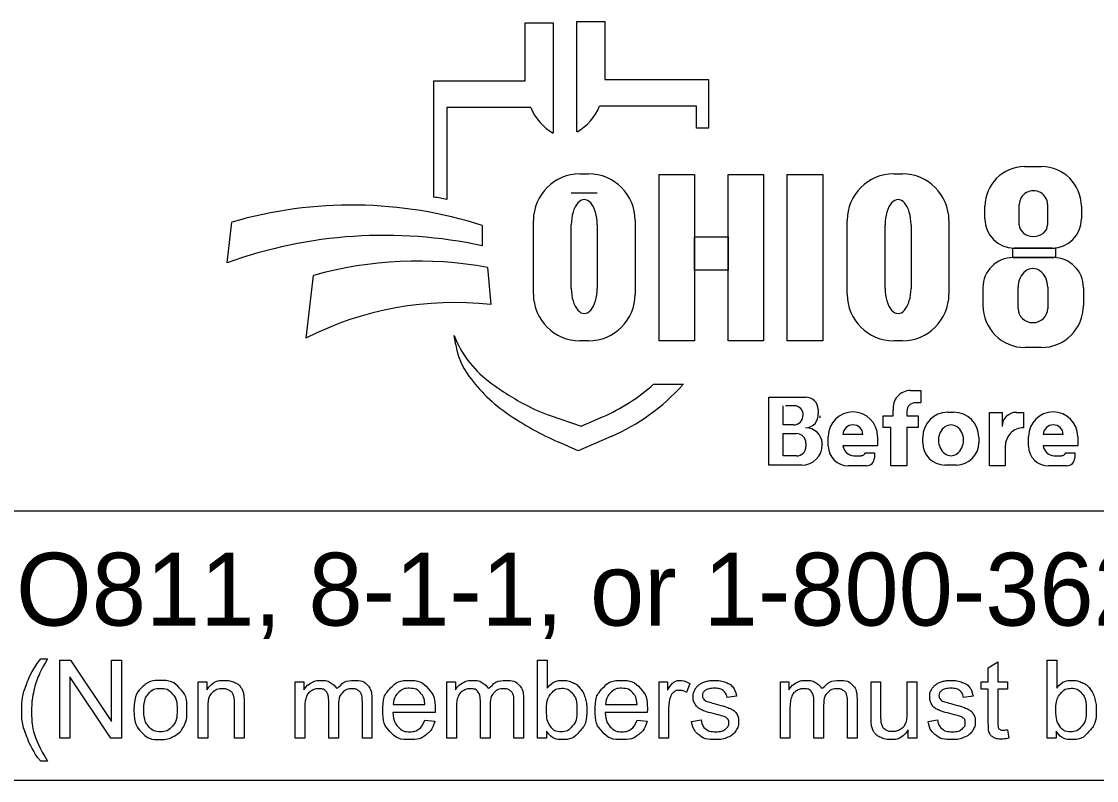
# Model space of a CAD drawing. Extents: x 0 to 34.3, y -4.1 to 22.
# Drawn here: x 10.115 to 12.181, y 7.738 to 9.198 of the extents above; entities that cross this region are included whole.
import ezdxf

# ---------------------------------------------------------------- set-up
doc = ezdxf.new("R2010")
doc.units = 0
doc.layers.add('GM_X_Adjacent_County', color=7, linetype='Continuous')
doc.layers.add('GM_X_Township', color=7, linetype='Continuous')

msp = doc.modelspace()

# ---------------------------------------------------------------- linework, layer by layer
at = {"layer": 'GM_X_Adjacent_County'}
for p, q in [((11.083, 9.0839), (11.083, 9.1953)), ((11.083, 9.1953), (11.1366, 9.1953)), ((11.1366, 9.1953), (11.1366, 8.9833)), ((11.1823, 8.9856), (11.1823, 9.1977)), ((11.1823, 9.1977), (11.2359, 9.1977)), ((11.2359, 9.1977), (11.2359, 9.0862)), ((10.907, 8.86), (10.907, 9.0839)), ((10.907, 9.0839), (11.083, 9.0839)), ((11.2359, 9.0862), (11.4352, 9.0862)), ((11.4352, 9.0862), (11.4352, 8.9924)), ((10.9323, 9.0324), (10.9323, 8.8556)), ((11.0934, 9.0324), (10.9323, 9.0324)), ((11.4119, 9.0347), (11.2255, 9.0347)), ((11.4119, 8.9924), (11.4119, 9.0347)), ((11.4352, 8.9924), (11.4119, 8.9924)), ((11.188, 8.9047), (11.2045, 8.9047)), ((11.791, 8.9047), (11.8076, 8.9047)), ((12.0426, 8.9187), (12.0753, 8.9187)), ((11.2212, 8.8677), (11.1714, 8.8677)), ((12.0324, 8.8067), (12.0324, 8.846)), ((12.0866, 8.846), (12.0866, 8.8067)), ((11.9663, 8.8181), (11.9663, 8.8424)), ((12.1516, 8.8424), (12.1516, 8.8181)), ((10.5097, 8.7337), (10.5191, 8.8118)), ((11.0003, 8.8053), (11.0003, 8.7665)), ((11.0985, 8.6732), (11.0985, 8.8152)), ((11.1714, 8.6846), (11.1714, 8.8069)), ((11.2212, 8.8069), (11.2212, 8.6846)), ((11.294, 8.8152), (11.294, 8.6732)), ((11.7016, 8.6732), (11.7016, 8.8152)), ((11.7745, 8.6846), (11.7745, 8.8069)), ((11.8243, 8.8069), (11.8243, 8.6846)), ((11.897, 8.8152), (11.897, 8.6732)), ((12.0956, 8.7621), (12.0223, 8.7621)), ((12.0204, 8.7438), (12.0978, 8.7438)), ((11.0103, 8.7247), (11.0165, 8.6537)), ((10.6615, 8.5891), (10.6762, 8.7093)), ((11.9626, 8.6518), (11.9626, 8.6859)), ((12.03, 8.6459), (12.03, 8.6868)), ((12.0869, 8.6868), (12.0869, 8.6459)), ((12.1557, 8.6859), (12.1557, 8.6518)), ((10.9492, 8.5762), (10.9461, 8.5942)), ((11.2045, 8.5837), (11.188, 8.5837)), ((11.8076, 8.5837), (11.791, 8.5837)), ((12.0747, 8.5709), (12.0435, 8.5709)), ((11.3295, 8.5004), (11.3869, 8.5004)), ((11.5508, 8.3446), (11.5508, 8.4753)), ((11.5508, 8.4753), (11.6219, 8.4753)), ((11.8234, 8.4881), (11.8428, 8.4881)), ((11.8428, 8.4881), (11.8428, 8.4651)), ((11.5787, 8.4219), (11.5787, 8.4588)), ((11.6039, 8.4588), (11.5827, 8.4588)), ((11.6457, 8.4516), (11.6457, 8.4437)), ((11.7901, 8.4397), (11.7901, 8.4502)), ((11.8428, 8.4647), (11.8327, 8.4647)), ((11.131, 8.44), (11.1905, 8.4195)), ((11.1905, 8.4195), (11.2315, 8.4373)), ((11.7708, 8.4168), (11.7708, 8.4397)), ((11.7708, 8.4397), (11.7901, 8.4397)), ((11.8162, 8.4482), (11.8162, 8.4397)), ((11.8162, 8.4397), (11.8377, 8.4397)), ((11.8377, 8.4397), (11.8377, 8.4168)), ((11.8946, 8.4463), (11.9067, 8.4463)), ((11.9748, 8.3434), (11.9748, 8.4461)), ((11.9748, 8.4461), (11.9994, 8.4461)), ((11.9994, 8.4461), (11.9994, 8.4192)), ((12.0266, 8.4461), (12.0405, 8.4461)), ((12.0405, 8.4461), (12.0405, 8.4164)), ((11.5982, 8.4219), (11.5787, 8.4219)), ((11.7857, 8.4168), (11.7708, 8.4168)), ((11.7857, 8.3434), (11.7857, 8.4168)), ((11.8377, 8.4168), (11.8162, 8.4168)), ((11.8162, 8.4168), (11.8162, 8.3434)), ((11.1845, 8.3725), (11.1471, 8.3889)), ((11.2477, 8.3999), (11.1845, 8.3725)), ((11.5787, 8.3624), (11.5787, 8.4053)), ((11.5787, 8.4053), (11.6043, 8.4053)), ((11.6653, 8.3814), (11.6653, 8.3998)), ((11.7319, 8.4038), (11.6934, 8.4038)), ((11.7599, 8.3998), (11.7599, 8.3821)), ((11.8468, 8.3877), (11.8468, 8.3985)), ((11.9545, 8.3985), (11.9545, 8.3877)), ((12.0502, 8.3814), (12.0502, 8.3998)), ((12.1168, 8.4038), (12.0783, 8.4038)), ((12.1448, 8.3998), (12.1448, 8.3821)), ((11.6224, 8.3872), (11.6224, 8.3808)), ((11.6538, 8.3843), (11.6538, 8.3839)), ((11.7599, 8.3821), (11.6934, 8.3821)), ((11.737, 8.3685), (11.7539, 8.3685)), ((11.7539, 8.3685), (11.7539, 8.3586)), ((12.0053, 8.3815), (12.0053, 8.3434)), ((12.1448, 8.3821), (12.0783, 8.3821)), ((12.122, 8.3685), (12.1388, 8.3685)), ((12.1388, 8.3685), (12.1388, 8.3586)), ((11.604, 8.3624), (11.5787, 8.3624)), ((11.7144, 8.3629), (11.7285, 8.3629)), ((12.0993, 8.3629), (12.1134, 8.3629)), ((11.6144, 8.3446), (11.5508, 8.3446)), ((11.7387, 8.3434), (11.7033, 8.3434)), ((11.8162, 8.3434), (11.7857, 8.3434)), ((11.9117, 8.3449), (11.8895, 8.3449)), ((12.0053, 8.3434), (11.9748, 8.3434)), ((12.1236, 8.3434), (12.0882, 8.3434))]:
    msp.add_line(p, q, dxfattribs=at)
for points in [[(11.3404, 8.9036), (11.4084, 8.9036), (11.4084, 8.5837), (11.3404, 8.5837)], [(11.4726, 8.9036), (11.5405, 8.9036), (11.5405, 8.5837), (11.4726, 8.5837)], [(11.5859, 8.9036), (11.6546, 8.9036), (11.6546, 8.5837), (11.5859, 8.5837)], [(11.4084, 8.7837), (11.4726, 8.7837), (11.4726, 8.7197), (11.4084, 8.7197)], [(12.0201, 8.7621), (12.1018, 8.7621), (12.1018, 8.7436), (12.0201, 8.7436)]]:
    msp.add_lwpolyline(points, close=True, dxfattribs=at)
for points in [[(10.1516, 7.9722), (10.1647, 7.9722)], [(10.1883, 7.8195), (10.1883, 7.9696), (10.2087, 7.9696), (10.2877, 7.8517), (10.2877, 7.9696), (10.3067, 7.9696), (10.3067, 7.8195), (10.2863, 7.8195), (10.2073, 7.9374), (10.2073, 7.8195), (10.1883, 7.8195)], [(11.1238, 7.8195), (11.1067, 7.8195), (11.1067, 7.9696), (11.1252, 7.9696), (11.1252, 7.9161)], [(11.9727, 7.8513), (11.9727, 7.914), (11.9591, 7.914), (11.9591, 7.9283), (11.9727, 7.9283), (11.9727, 7.9553), (11.9912, 7.9663), (11.9912, 7.9283), (12.0096, 7.9283), (12.0096, 7.914), (11.9912, 7.914), (11.9912, 7.8503)], [(12.1029, 7.8195), (12.0858, 7.8195), (12.0858, 7.9696), (12.1042, 7.9696), (12.1042, 7.9161)], [(10.4543, 7.8195), (10.4543, 7.9283), (10.4709, 7.9283), (10.4709, 7.9129)], [(10.6407, 7.8195), (10.6407, 7.9283), (10.6572, 7.9283), (10.6572, 7.913)], [(10.9321, 7.8195), (10.9321, 7.9283), (10.9486, 7.9283), (10.9486, 7.913)], [(11.3399, 7.8195), (11.3399, 7.9283), (11.3565, 7.9283), (11.3565, 7.9118)], [(11.3989, 7.9248), (11.3925, 7.9078)], [(11.5731, 7.8195), (11.5731, 7.9283), (11.5896, 7.9283), (11.5896, 7.913)], [(11.7474, 7.8609), (11.7474, 7.9283), (11.7658, 7.9283), (11.7658, 7.868)], [(11.8171, 7.8701), (11.8171, 7.9283), (11.8355, 7.9283), (11.8355, 7.8195), (11.819, 7.8195)], [(10.7882, 7.8942), (10.7882, 7.8195), (10.7698, 7.8195), (10.7698, 7.888)], [(11.0796, 7.8942), (11.0796, 7.8195), (11.0612, 7.8195), (11.0612, 7.888)], [(11.4889, 7.9002), (11.4708, 7.8978)], [(11.7206, 7.8942), (11.7206, 7.8195), (11.7022, 7.8195), (11.7022, 7.888)], [(11.9434, 7.9002), (11.9253, 7.8978)], [(10.4727, 7.8789), (10.4727, 7.8195), (10.4543, 7.8195)], [(10.5426, 7.8864), (10.5426, 7.8195), (10.5242, 7.8195), (10.5242, 7.8856)], [(10.6591, 7.8759), (10.6591, 7.8195), (10.6407, 7.8195)], [(10.7238, 7.8827), (10.7238, 7.8195), (10.7054, 7.8195), (10.7054, 7.8901)], [(10.8293, 7.8843), (10.8901, 7.8843)], [(10.9505, 7.8759), (10.9505, 7.8195), (10.9321, 7.8195)], [(11.0152, 7.8827), (11.0152, 7.8195), (10.9967, 7.8195), (10.9967, 7.8901)], [(11.2373, 7.8843), (11.2981, 7.8843)], [(11.3583, 7.8765), (11.3583, 7.8195), (11.3399, 7.8195)], [(11.5915, 7.8759), (11.5915, 7.8195), (11.5731, 7.8195)], [(11.6562, 7.8827), (11.6562, 7.8195), (11.6377, 7.8195), (11.6377, 7.8901)], [(10.9094, 7.8692), (10.8283, 7.8692)], [(10.8899, 7.8546), (10.9089, 7.8522)], [(11.3174, 7.8692), (11.2363, 7.8692)], [(11.2979, 7.8546), (11.3169, 7.8522)], [(11.4025, 7.852), (11.4207, 7.8548)], [(11.857, 7.852), (11.8752, 7.8548)], [(11.1238, 7.8331), (11.1238, 7.8195)], [(11.819, 7.8195), (11.819, 7.8355)], [(12.0096, 7.8359), (12.0122, 7.8196)], [(12.1029, 7.8331), (12.1029, 7.8195)], [(10.1647, 7.7753), (10.1516, 7.7753)]]:
    msp.add_lwpolyline(points, dxfattribs=at)
for centre, radius, start, end in [((11.1847, 9.0692), 0.0985, 201.9296, 240.7469), ((11.1342, 9.0715), 0.0985, 299.2531, 338.0704), ((11.188, 8.8152), 0.0895, 90, 180), ((11.2045, 8.8152), 0.0895, 0, 90), ((11.791, 8.8152), 0.0895, 90, 180), ((11.8076, 8.8152), 0.0895, 0, 90), ((12.0426, 8.8424), 0.0763, 90, 180), ((12.0753, 8.8424), 0.0763, 0, 90), ((10.7491, 8.0257), 0.8191, 72.1402, 106.3144), ((10.7789, 8.051), 0.8191, 79.2074, 81.0007), ((12.0223, 8.8181), 0.056, 180, 270), ((12.0956, 8.8181), 0.056, 270, 0), ((10.8122, 7.8946), 0.8919, 77.8238, 109.8274), ((12.0204, 8.6859), 0.0579, 90, 180), ((12.0978, 8.6859), 0.0579, 0, 90), ((10.8761, 8.0049), 0.7322, 79.44, 105.8467), ((10.9481, 8.0217), 0.6357, 83.8248, 116.8021), ((11.188, 8.6732), 0.0895, 180, 270), ((11.2045, 8.6732), 0.0895, 270, 0), ((11.791, 8.6732), 0.0895, 180, 270), ((11.8076, 8.6732), 0.0895, 270, 0), ((12.0435, 8.6518), 0.081, 180, 270), ((12.0747, 8.6518), 0.081, 270, 0), ((11.1335, 8.6663), 0.2008, 201.0457, 232.5314), ((11.0905, 8.6003), 0.1433, 189.6817, 216.0884), ((11.2242, 8.6978), 0.3088, 216.0884, 235.7167), ((11.3261, 8.9175), 0.5173, 232.5314, 241.794), ((11.0881, 8.7678), 0.3602, 293.4582, 312.0712), ((11.0881, 8.7678), 0.401, 293.4582, 317.8286), ((11.6219, 8.4516), 0.0238, 0, 90), ((11.8234, 8.4546), 0.0335, 90, 187.5187), ((11.2409, 8.7587), 0.3371, 241.794, 250.9821), ((11.6, 8.4419), 0.0169, 357.8325, 90), ((11.8327, 8.4482), 0.0165, 90, 180), ((11.3907, 8.942), 0.6044, 235.7167, 246.2325), ((11.5982, 8.4406), 0.0187, 270, 2.0582), ((11.6216, 8.4409), 0.0243, 270, 6.6529), ((11.6321, 8.4394), 0.0175, 347.4023, 0), ((11.7126, 8.3998), 0.0473, 0, 180), ((11.8946, 8.3985), 0.0478, 90, 180), ((11.9067, 8.3985), 0.0478, 0, 90), ((12.0263, 8.4192), 0.0269, 89.2449, 180), ((12.0975, 8.3998), 0.0473, 0, 180), ((11.6217, 8.3845), 0.0321, 4.0748, 90), ((11.7126, 8.4028), 0.0193, 2.9632, 177.0368), ((12.0403, 8.3815), 0.0349, 89.6033, 180), ((12.0976, 8.4028), 0.0193, 2.9632, 177.0368), ((11.6043, 8.3872), 0.0181, 0, 90), ((11.6208, 8.3843), 0.033, 0, 11.7502), ((11.604, 8.3808), 0.0184, 270, 0), ((11.6144, 8.3839), 0.0393, 270, 0), ((11.7033, 8.3814), 0.038, 180, 270), ((11.7144, 8.3839), 0.021, 184.827, 270), ((11.7285, 8.3723), 0.00938, 270, 335.9979), ((11.8895, 8.3877), 0.0428, 180, 270), ((11.9117, 8.3877), 0.0428, 270, 0), ((12.0882, 8.3814), 0.038, 180, 270), ((12.0993, 8.3839), 0.021, 184.827, 270), ((12.1134, 8.3723), 0.00938, 270, 335.9979), ((11.7387, 8.3586), 0.0152, 270, 0), ((12.1236, 8.3586), 0.0152, 270, 0)]:
    msp.add_arc(centre, radius, start, end, dxfattribs=at)
for centre, major_axis, ratio, start_param, end_param in [((12.0595, 8.846), (0.0271, 0), 0.969373, 0, 3.141593), ((11.1963, 8.8069), (0, 0.0484), 0.514403, 4.712389, 7.853982), ((11.7994, 8.8069), (0, 0.0484), 0.514403, 4.712389, 7.853982), ((12.0595, 8.8067), (0.0271, 0), 0.818453, 3.141593, 6.283185), ((12.0585, 8.6868), (0, 0.0358), 0.794529, 4.712389, 7.853982), ((11.1963, 8.6846), (0, 0.0484), 0.514403, 1.570796, 4.712389), ((11.7994, 8.6846), (0, 0.0484), 0.514403, 1.570796, 4.712389), ((12.0585, 8.6459), (0.0284, 0), 0.959837, 3.141593, 6.283185), ((11.9011, 8.3931), (0, 0.029), 0.832186, 4.712389, 7.853982), ((11.9011, 8.3931), (0, 0.0302), 0.797287, 1.570796, 4.712389)]:
    msp.add_ellipse(centre, major_axis=major_axis, ratio=ratio, start_param=start_param, end_param=end_param, dxfattribs=at)
for points in [[(10.1516, 7.7753), (10.1363, 7.7946), (10.1258, 7.8204), (10.1152, 7.8462), (10.1152, 7.8738), (10.1152, 7.8982), (10.1231, 7.9205), (10.1323, 7.9464), (10.1516, 7.9722)], [(10.1647, 7.9722), (10.1524, 7.9508), (10.1484, 7.9417), (10.1422, 7.9276), (10.1386, 7.9122), (10.1342, 7.8931), (10.1342, 7.8737), (10.1342, 7.8245), (10.1647, 7.7753)], [(10.3308, 7.8739), (10.3308, 7.9041), (10.3476, 7.9186), (10.3616, 7.9307), (10.3818, 7.9307), (10.4042, 7.9307), (10.4184, 7.916), (10.4327, 7.9013), (10.4327, 7.8754), (10.4327, 7.8545), (10.4264, 7.8424), (10.4201, 7.8304), (10.408, 7.8237), (10.396, 7.8171), (10.3818, 7.8171), (10.359, 7.8171), (10.3449, 7.8317), (10.3308, 7.8464), (10.3308, 7.8739)], [(10.3498, 7.8739), (10.3498, 7.853), (10.3589, 7.8426), (10.368, 7.8322), (10.3818, 7.8322), (10.3955, 7.8322), (10.4046, 7.8426), (10.4137, 7.8531), (10.4137, 7.8745), (10.4137, 7.8947), (10.4045, 7.9051), (10.3954, 7.9155), (10.3818, 7.9155), (10.368, 7.9155), (10.3589, 7.9052), (10.3498, 7.8948), (10.3498, 7.8739)], [(10.4709, 7.9129), (10.4829, 7.9307), (10.5055, 7.9307), (10.5153, 7.9307), (10.5236, 7.9272), (10.5318, 7.9237), (10.5359, 7.9179), (10.54, 7.9122), (10.5416, 7.9043), (10.5426, 7.8992), (10.5426, 7.8864)], [(10.5242, 7.8856), (10.5242, 7.8969), (10.5221, 7.9025), (10.5199, 7.908), (10.5144, 7.9114), (10.509, 7.9147), (10.5016, 7.9147), (10.4898, 7.9147), (10.4813, 7.9072), (10.4727, 7.8998), (10.4727, 7.8789)], [(10.6572, 7.913), (10.6623, 7.921), (10.6708, 7.9258), (10.6793, 7.9307), (10.6902, 7.9307), (10.7023, 7.9307), (10.71, 7.9257), (10.7177, 7.9207), (10.7209, 7.9116), (10.7338, 7.9307), (10.7546, 7.9307), (10.7708, 7.9307), (10.7795, 7.9218), (10.7882, 7.9128), (10.7882, 7.8942)], [(10.7054, 7.8901), (10.7054, 7.9024), (10.7009, 7.9086), (10.6963, 7.9147), (10.6861, 7.9147), (10.6783, 7.9147), (10.6717, 7.9106), (10.6651, 7.9065), (10.6621, 7.8986), (10.6591, 7.8907), (10.6591, 7.8759)], [(10.7698, 7.888), (10.7698, 7.899), (10.768, 7.9039), (10.7662, 7.9088), (10.7615, 7.9117), (10.7568, 7.9147), (10.7504, 7.9147), (10.739, 7.9147), (10.7314, 7.9071), (10.7238, 7.8994), (10.7238, 7.8827)], [(10.9089, 7.8522), (10.9044, 7.8355), (10.8922, 7.8263), (10.8801, 7.8171), (10.8611, 7.8171), (10.8373, 7.8171), (10.8233, 7.8318), (10.8093, 7.8465), (10.8093, 7.873), (10.8093, 7.9004), (10.8234, 7.9156), (10.8376, 7.9307), (10.8601, 7.9307), (10.8819, 7.9307), (10.8957, 7.9159), (10.9095, 7.901), (10.9095, 7.8741), (10.9095, 7.8724), (10.9094, 7.8692)], [(10.8901, 7.8843), (10.8889, 7.898), (10.8831, 7.9049), (10.8743, 7.9156), (10.8603, 7.9156), (10.8476, 7.9156), (10.8389, 7.9071), (10.8302, 7.8986), (10.8293, 7.8843)], [(10.9486, 7.913), (10.9537, 7.921), (10.9622, 7.9258), (10.9707, 7.9307), (10.9816, 7.9307), (10.9936, 7.9307), (11.0014, 7.9257), (11.0091, 7.9207), (11.0123, 7.9116), (11.0252, 7.9307), (11.0459, 7.9307), (11.0622, 7.9307), (11.0709, 7.9218), (11.0796, 7.9128), (11.0796, 7.8942)], [(10.9967, 7.8901), (10.9967, 7.9024), (10.9922, 7.9086), (10.9877, 7.9147), (10.9775, 7.9147), (10.9697, 7.9147), (10.9631, 7.9106), (10.9564, 7.9065), (10.9535, 7.8986), (10.9505, 7.8907), (10.9505, 7.8759)], [(11.0612, 7.888), (11.0612, 7.899), (11.0594, 7.9039), (11.0576, 7.9088), (11.0529, 7.9117), (11.0482, 7.9147), (11.0418, 7.9147), (11.0303, 7.9147), (11.0227, 7.9071), (11.0152, 7.8994), (11.0152, 7.8827)], [(11.1236, 7.8747), (11.1236, 7.8551), (11.1289, 7.8464), (11.1376, 7.8322), (11.1524, 7.8322), (11.1645, 7.8322), (11.1732, 7.8427), (11.182, 7.8532), (11.182, 7.874), (11.182, 7.8953), (11.1736, 7.9055), (11.1652, 7.9156), (11.1532, 7.9156), (11.1411, 7.9156), (11.1324, 7.9051), (11.1236, 7.8946), (11.1236, 7.8747)], [(11.1252, 7.9161), (11.1368, 7.9307), (11.155, 7.9307), (11.165, 7.9307), (11.174, 7.9267), (11.1829, 7.9226), (11.1887, 7.9153), (11.1945, 7.908), (11.1978, 7.8977), (11.201, 7.8873), (11.201, 7.8755), (11.201, 7.8476), (11.1872, 7.8323), (11.1734, 7.8171), (11.154, 7.8171), (11.1347, 7.8171), (11.1238, 7.8331)], [(11.3169, 7.8522), (11.3124, 7.8355), (11.3002, 7.8263), (11.288, 7.8171), (11.2691, 7.8171), (11.2452, 7.8171), (11.2313, 7.8318), (11.2173, 7.8465), (11.2173, 7.873), (11.2173, 7.9004), (11.2314, 7.9156), (11.2456, 7.9307), (11.2681, 7.9307), (11.2899, 7.9307), (11.3037, 7.9159), (11.3175, 7.901), (11.3175, 7.8741), (11.3175, 7.8724), (11.3174, 7.8692)], [(11.2981, 7.8843), (11.2969, 7.898), (11.2911, 7.9049), (11.2823, 7.9156), (11.2683, 7.9156), (11.2556, 7.9156), (11.2469, 7.9071), (11.2382, 7.8986), (11.2373, 7.8843)], [(11.3565, 7.9118), (11.3628, 7.9234), (11.3682, 7.927), (11.3735, 7.9307), (11.38, 7.9307), (11.3893, 7.9307), (11.3989, 7.9248)], [(11.4708, 7.8978), (11.4695, 7.9062), (11.4637, 7.9109), (11.4578, 7.9156), (11.447, 7.9156), (11.4343, 7.9156), (11.4288, 7.9114), (11.4234, 7.9072), (11.4234, 7.9016), (11.4234, 7.898), (11.4257, 7.8951), (11.4279, 7.8921), (11.4327, 7.8902), (11.4355, 7.8891), (11.449, 7.8855), (11.4686, 7.8802), (11.4764, 7.8769), (11.4841, 7.8736), (11.4886, 7.8672), (11.493, 7.8609), (11.493, 7.8515), (11.493, 7.8423), (11.4876, 7.8341), (11.4822, 7.826), (11.472, 7.8215), (11.4619, 7.8171), (11.4491, 7.8171), (11.4278, 7.8171), (11.4167, 7.8259), (11.4055, 7.8347), (11.4025, 7.852)], [(11.4207, 7.8548), (11.4222, 7.8439), (11.4292, 7.838), (11.4363, 7.8322), (11.4489, 7.8322), (11.4617, 7.8322), (11.4678, 7.8374), (11.474, 7.8425), (11.474, 7.8495), (11.474, 7.8558), (11.4685, 7.8594), (11.4647, 7.8618), (11.4497, 7.8656), (11.4293, 7.8708), (11.4215, 7.8745), (11.4137, 7.8782), (11.4096, 7.8848), (11.4055, 7.8914), (11.4055, 7.8994), (11.4055, 7.9067), (11.4089, 7.9129), (11.4122, 7.9191), (11.418, 7.9232), (11.4223, 7.9263), (11.4297, 7.9285), (11.4371, 7.9307), (11.4457, 7.9307), (11.4585, 7.9307), (11.4682, 7.927), (11.4779, 7.9233), (11.4825, 7.917), (11.4871, 7.9107), (11.4889, 7.9002)], [(11.5896, 7.913), (11.5947, 7.921), (11.6032, 7.9258), (11.6117, 7.9307), (11.6225, 7.9307), (11.6346, 7.9307), (11.6424, 7.9257), (11.6501, 7.9207), (11.6533, 7.9116), (11.6662, 7.9307), (11.6869, 7.9307), (11.7032, 7.9307), (11.7119, 7.9218), (11.7206, 7.9128), (11.7206, 7.8942)], [(11.6377, 7.8901), (11.6377, 7.9024), (11.6332, 7.9086), (11.6287, 7.9147), (11.6185, 7.9147), (11.6107, 7.9147), (11.6041, 7.9106), (11.5974, 7.9065), (11.5945, 7.8986), (11.5915, 7.8907), (11.5915, 7.8759)], [(11.7022, 7.888), (11.7022, 7.899), (11.7004, 7.9039), (11.6986, 7.9088), (11.6939, 7.9117), (11.6892, 7.9147), (11.6828, 7.9147), (11.6713, 7.9147), (11.6637, 7.9071), (11.6562, 7.8994), (11.6562, 7.8827)], [(11.9253, 7.8978), (11.9241, 7.9062), (11.9182, 7.9109), (11.9123, 7.9156), (11.9016, 7.9156), (11.8888, 7.9156), (11.8834, 7.9114), (11.878, 7.9072), (11.878, 7.9016), (11.878, 7.898), (11.8802, 7.8951), (11.8825, 7.8921), (11.8873, 7.8902), (11.8901, 7.8891), (11.9036, 7.8855), (11.9232, 7.8802), (11.931, 7.8769), (11.9387, 7.8736), (11.9431, 7.8672), (11.9476, 7.8609), (11.9476, 7.8515), (11.9476, 7.8423), (11.9422, 7.8341), (11.9368, 7.826), (11.9266, 7.8215), (11.9165, 7.8171), (11.9036, 7.8171), (11.8824, 7.8171), (11.8712, 7.8259), (11.8601, 7.8347), (11.857, 7.852)], [(11.8752, 7.8548), (11.8768, 7.8439), (11.8838, 7.838), (11.8908, 7.8322), (11.9035, 7.8322), (11.9162, 7.8322), (11.9224, 7.8374), (11.9286, 7.8425), (11.9286, 7.8495), (11.9286, 7.8558), (11.9231, 7.8594), (11.9193, 7.8618), (11.9042, 7.8656), (11.8839, 7.8708), (11.8761, 7.8745), (11.8682, 7.8782), (11.8642, 7.8848), (11.8601, 7.8914), (11.8601, 7.8994), (11.8601, 7.9067), (11.8635, 7.9129), (11.8668, 7.9191), (11.8725, 7.9232), (11.8768, 7.9263), (11.8843, 7.9285), (11.8917, 7.9307), (11.9002, 7.9307), (11.9131, 7.9307), (11.9228, 7.927), (11.9325, 7.9233), (11.9371, 7.917), (11.9417, 7.9107), (11.9434, 7.9002)], [(12.1026, 7.8747), (12.1026, 7.8551), (12.1079, 7.8464), (12.1166, 7.8322), (12.1315, 7.8322), (12.1435, 7.8322), (12.1523, 7.8427), (12.1611, 7.8532), (12.1611, 7.874), (12.1611, 7.8953), (12.1527, 7.9055), (12.1442, 7.9156), (12.1323, 7.9156), (12.1202, 7.9156), (12.1114, 7.9051), (12.1026, 7.8946), (12.1026, 7.8747)], [(12.1042, 7.9161), (12.1159, 7.9307), (12.134, 7.9307), (12.1441, 7.9307), (12.153, 7.9267), (12.162, 7.9226), (12.1678, 7.9153), (12.1735, 7.908), (12.1768, 7.8977), (12.1801, 7.8873), (12.1801, 7.8755), (12.1801, 7.8476), (12.1663, 7.8323), (12.1524, 7.8171), (12.1331, 7.8171), (12.1138, 7.8171), (12.1029, 7.8331)], [(11.3925, 7.9078), (11.3857, 7.9117), (11.379, 7.9117), (11.373, 7.9117), (11.3682, 7.9081), (11.3634, 7.9045), (11.3614, 7.898), (11.3583, 7.8882), (11.3583, 7.8765)], [(10.8283, 7.8692), (10.8293, 7.8512), (10.8384, 7.8417), (10.8476, 7.8322), (10.8612, 7.8322), (10.8713, 7.8322), (10.8785, 7.8375), (10.8857, 7.8429), (10.8899, 7.8546)], [(11.2363, 7.8692), (11.2373, 7.8512), (11.2464, 7.8417), (11.2556, 7.8322), (11.2692, 7.8322), (11.2793, 7.8322), (11.2865, 7.8375), (11.2937, 7.8429), (11.2979, 7.8546)], [(11.819, 7.8355), (11.8063, 7.8171), (11.7845, 7.8171), (11.7749, 7.8171), (11.7666, 7.8208), (11.7582, 7.8245), (11.7542, 7.83), (11.7502, 7.8356), (11.7485, 7.8437), (11.7474, 7.8491), (11.7474, 7.8609)], [(11.7658, 7.868), (11.7658, 7.8536), (11.7669, 7.8486), (11.7687, 7.8413), (11.7743, 7.8371), (11.7799, 7.833), (11.7882, 7.833), (11.7965, 7.833), (11.8038, 7.8372), (11.811, 7.8415), (11.8141, 7.8488), (11.8171, 7.8561), (11.8171, 7.8701)], [(12.0122, 7.8196), (12.0044, 7.818), (11.9983, 7.818), (11.9883, 7.818), (11.9828, 7.8212), (11.9772, 7.8244), (11.975, 7.8295), (11.9727, 7.8347), (11.9727, 7.8513)], [(11.9912, 7.8503), (11.9912, 7.8424), (11.9921, 7.8401), (11.9931, 7.8378), (11.9953, 7.8365), (11.9975, 7.8352), (12.0015, 7.8352), (12.0046, 7.8352), (12.0096, 7.8359)]]:
    msp.add_open_spline(points, degree=3, dxfattribs=at)
at = {"layer": 'GM_X_Township'}
for p, q in [((13.977, 8.2562), (9.727, 8.2562)), ((13.977, 7.7384), (9.727, 7.7384))]:
    msp.add_line(p, q, dxfattribs=at)

# ---------------------------------------------------------------- texts
at = {"layer": 'GM_X_Adjacent_County'}
msp.add_text('OHIO811, 8-1-1, or 1-800-362-2764', height=0.14, dxfattribs=at).set_placement((9.7714, 8.0362))

doc.saveas('drawing.dxf')
